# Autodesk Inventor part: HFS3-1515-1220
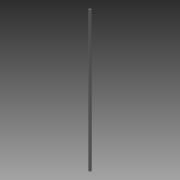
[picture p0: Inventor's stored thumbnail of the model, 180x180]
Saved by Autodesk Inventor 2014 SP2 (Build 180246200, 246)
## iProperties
Created: 2019-03
Part Number: HFS3-1515-1220
Material: Generic
Catalog Web Link: www.cadenas.de
Description: HFS3, KHFS3-Aluminum Frames 15mm Square
Vendor: MISUMI
Document SubType Name: Modeling
Designer: psadmin
Manufacturer: MISUMI
Mass: 153.006 g
Surface Area: 1430.69 cm^2
Volume: 153.006 cm^3
Density: 1 g/cm^3
Appearance: PSOLRGB-175-175-175
Category: PARTsolutions
Company: MISUMI
Title: HFS3-1515-1220
Author: Cadenas PARTsolutions
Comments: Aluminum Frames 15mm Square
L: 1220
PSOL_IDENT_0: {$CADENAS_DATA\23d-libs\misumi\metric\38_al_extrusions_blackets\hfs3_1515.prj},175 {VTYP=3D},{NB=HFS
PSOL_IDENT_1: 3-1515-1220},{LINA=HFS3-1515-1220},{NN=HFS3, KHFS3},{DATE=30.03.2018 06:55:53},{GEOMDATE=07.03.2008
PSOL_IDENT_2: 00:00:00},{VERSION=},{LINEID=10},{WBVAR=L},{WBNUMERIC=L}  {NB=HFS3-1515-1220},{LINA=HFS3-1515-1220},
PSOL_IDENT_3: {KT=LINA},{PN=HFS3-1515-1220},{MAT=A6N01SS-T5(Aluminum)(EN AC-51400_AlMgSiO,7-T5)},{ST=Alumite},{LT=
PSOL_IDENT_4: Specified Length},{L=1220.0},{FEAT=4 Slots},{LALG=[50-2000/0.5]},{LTOL=+/- 0.5},{MASS=0.34},{SA=126}
PSOL_IDENT_5: ,{SMILX=0.280x10^4},{SMILY=0.280x10^4},{TYPE=HFS3-1515}
NN: HFS3, KHFS3
NT: Aluminum Frames 15mm Square
NB: HFS3-1515-1220
NBSYN: $PN.
LINA: HFS3-1515-1220
PN: HFS3-1515-1220
MAT: A6N01SS-T5
ST: Clear Anodizing
LT: Specified Length
LTOL: +/- 0.5
MASS: 0.34
SA: 126
SMILX: 0.280x10^4
SMILY: 0.280x10^4
SUPPLIER: MISUMI
ARTICLENO: HFS3-1515-1220
BOMINFO: HFS3-1515-1220
CREATOR: CADENAS GmbH
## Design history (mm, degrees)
sketch "Sketch_1"
  geometry: L1 (-7.2, 1.7)-(-6.4, 1.7); L2 (-6.4, 1.7)-(-6.4, 2.85); L3 (-6.4, 2.85)-(-3.8, 2.85); L4 (-3.8, 2.85)-(-2.8, 1.85); L5 (-2.8, 1.85)-(-2.8, 0.52); L6 (-2.8, 0.52)-(-2.5, 0); L7 (-2.5, 0)-(-2.8, -0.52); L8 (-2.8, -0.52)-(-2.8, -1.85); L9 (-2.8, -1.85)-(-3.8, -2.85); L10 (-3.8, -2.85)-(-6.4, -2.85); L11 (-6.4, -2.85)-(-6.4, -1.7); L12 (-6.4, -1.7)-(-7.2, -1.7); L13 (-7.5, -2)-(-7.5, -6.5); L14 (-6.5, -7.5)-(-2, -7.5); L15 (-1.7, -7.2)-(-1.7, -6.4); L16 (-1.7, -6.4)-(-2.85, -6.4); L17 (-2.85, -6.4)-(-2.85, -3.8); L18 (-2.85, -3.8)-(-1.85, -2.8); L19 (-1.85, -2.8)-(-0.52, -2.8); L20 (-0.52, -2.8)-(0, -2.5); L21 (0, -2.5)-(0.52, -2.8); L22 (0.52, -2.8)-(1.85, -2.8); L23 (1.85, -2.8)-(2.85, -3.8); L24 (2.85, -3.8)-(2.85, -6.4); L25 (2.85, -6.4)-(1.7, -6.4); L26 (1.7, -6.4)-(1.7, -7.2); L27 (2, -7.5)-(6.5, -7.5); L28 (7.5, -6.5)-(7.5, -2); L29 (7.2, -1.7)-(6.4, -1.7); L30 (6.4, -1.7)-(6.4, -2.85); L31 (6.4, -2.85)-(3.8, -2.85); L32 (3.8, -2.85)-(2.8, -1.85); L33 (2.8, -1.85)-(2.8, -0.52); L34 (2.8, -0.52)-(2.5, 0); L35 (2.5, 0)-(2.8, 0.52); L36 (2.8, 0.52)-(2.8, 1.85); L37 (2.8, 1.85)-(3.8, 2.85); L38 (3.8, 2.85)-(6.4, 2.85); L39 (6.4, 2.85)-(6.4, 1.7); L40 (6.4, 1.7)-(7.2, 1.7); L41 (7.5, 2)-(7.5, 6.5); L42 (6.5, 7.5)-(2, 7.5); L43 (1.7, 7.2)-(1.7, 6.4); L44 (1.7, 6.4)-(2.85, 6.4); L45 (2.85, 6.4)-(2.85, 3.8); L46 (2.85, 3.8)-(1.85, 2.8); L47 (1.85, 2.8)-(0.52, 2.8); L48 (0.52, 2.8)-(0, 2.5); L49 (0, 2.5)-(-0.52, 2.8); L50 (-0.52, 2.8)-(-1.85, 2.8); L51 (-1.85, 2.8)-(-2.85, 3.8); L52 (-2.85, 3.8)-(-2.85, 6.4); L53 (-2.85, 6.4)-(-1.7, 6.4); L54 (-1.7, 6.4)-(-1.7, 7.2); L55 (-2, 7.5)-(-6.5, 7.5); L56 (-7.5, 6.5)-(-7.5, 2); C1 r 1.25 at (0, 0); A1 r 0.3 centre (-7.2, 2) between (-7.5, 2) and (-7.2, 1.7); A2 r 0.3 centre (-7.2, -2) between (-7.2, -1.7) and (-7.5, -2); A3 r 1 centre (-6.5, -6.5) between (-7.5, -6.5) and (-6.5, -7.5); A4 r 0.3 centre (-2, -7.2) between (-2, -7.5) and (-1.7, -7.2); A5 r 0.3 centre (2, -7.2) between (1.7, -7.2) and (2, -7.5); A6 r 1 centre (6.5, -6.5) between (6.5, -7.5) and (7.5, -6.5); A7 r 0.3 centre (7.2, -2) between (7.5, -2) and (7.2, -1.7); A8 r 0.3 centre (7.2, 2) between (7.2, 1.7) and (7.5, 2); A9 r 1 centre (6.5, 6.5) between (7.5, 6.5) and (6.5, 7.5); A10 r 0.3 centre (2, 7.2) between (2, 7.5) and (1.7, 7.2); A11 r 0.3 centre (-2, 7.2) between (-1.7, 7.2) and (-2, 7.5); A12 r 1 centre (-6.5, 6.5) between (-6.5, 7.5) and (-7.5, 6.5); 1 further point
  constraints: 112 end point, 24 point on circle, 13 centre point
extrude "Extrusion1" join sketch "Sketch_1" distance "d0" = 1220 (= L); taper "d1" = 0 deg
body "Solid1"
other parameters: "L" = 1220 [user parameter; used in 1 equation term]
